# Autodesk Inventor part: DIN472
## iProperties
Shininess: 64.0
Angle Display Precision: 2
Document Length Units: 11269
Document Angle Units: 11279
Document Time Units: 11290
Document Mass Units: 11283
Document Length Units Precision: 3
Document Angle Units Precision: 2
Compacted: True
Created: 2006-01
Part Number: DIN472
Material: Federstahl
Catalog Web Link: www.seeger-orbis.de
Description: Sicherungsring
Document SubType Name: Modeling
Density: 0.0
Volumn: 0.0
Area: 0.0
PropertySet Name: Model Information
Control State: 0
Master: False
Checked Out: False
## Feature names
1. Extrusion2
